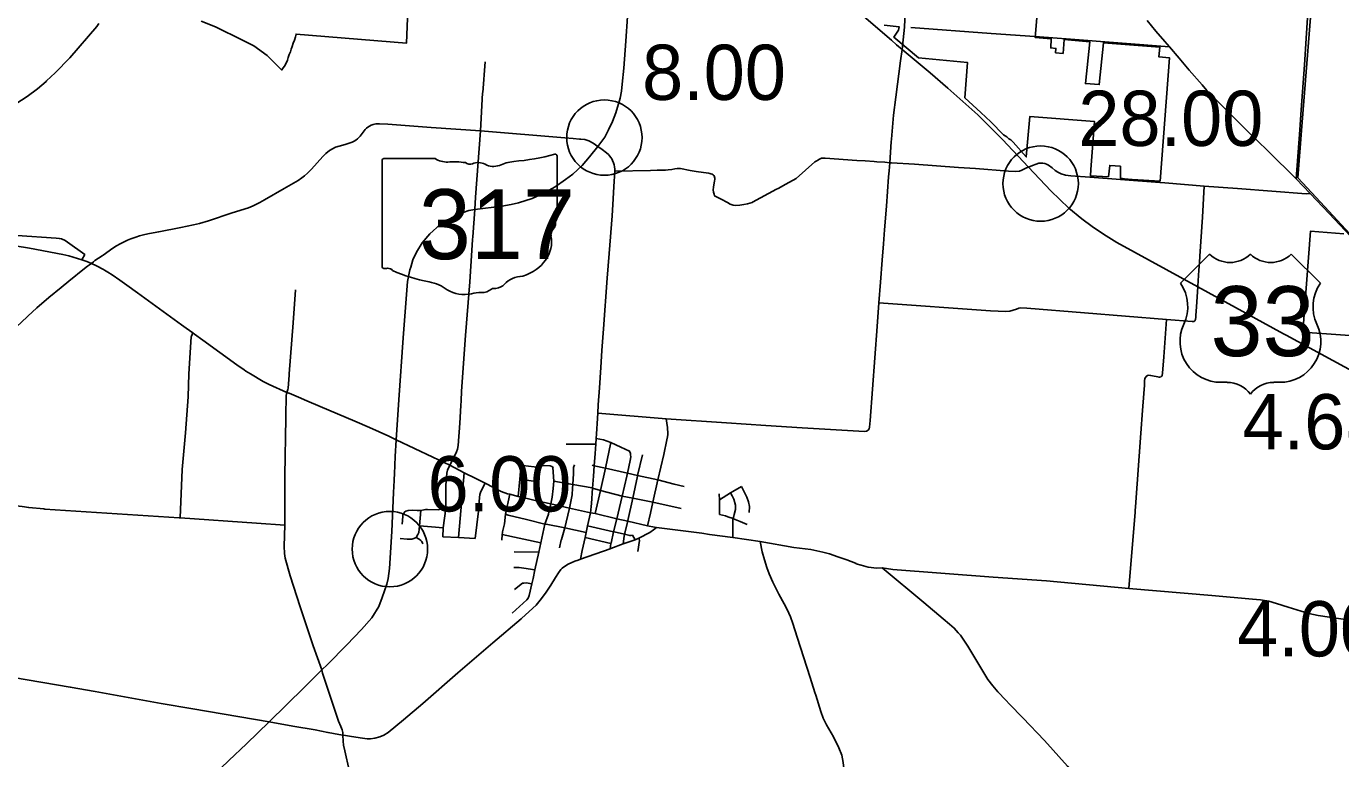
# Model space of a CAD drawing. Extents: x 1659811 to 1934326, y 644115 to 934867.
# Drawn here: x 1848780 to 1874937, y 669837 to 684419 of the extents above; entities that cross this region are included whole.
import ezdxf

# ---------------------------------------------------------------- set-up
doc = ezdxf.new("R2010")
doc.units = 0
for name, color, linetype in [('Default', 7, 'Continuous'), ('GM_X_City_Street', 7, 'Continuous'), ('GM_X_Corporation', 7, 'Continuous'), ('GM_X_County_Road', 7, 'Continuous'), ('GM_X_Interstate_Route', 7, 'Continuous'), ('GM_X_State_Route', 7, 'Continuous'), ('GM_X_State_Shield', 7, 'Continuous'), ('GM_X_Township_Road', 7, 'Continuous'), ('GM_X_US_Route', 7, 'Continuous'), ('GM_X_US_Shield', 7, 'Continuous')]:
    doc.layers.add(name, color=color, linetype=linetype)

msp = doc.modelspace()

# ---------------------------------------------------------------- linework, layer by layer
at = {"layer": 'Default'}
for centre in [(1860284, 682203), (1868966, 681287), (1856015, 674010)]:
    msp.add_circle(centre, 750, dxfattribs=at)
at = {"layer": 'GM_X_City_Street'}
for points in [[(1866232, 684150), (1866259, 684403), (1866289, 685179), (1866306, 685614)], [(1866382, 684394), (1867983, 684278), (1868853, 684214)], [(1857862, 683100), (1857912, 683710)], [(1857819, 682336), (1857861, 683093), (1857862, 683100)], [(1850291, 679851), (1850307, 679862), (1850502, 679999), (1850578, 680046), (1850646, 680085), (1850729, 680130), (1850795, 680161), (1850860, 680186), (1850958, 680222), (1851033, 680246), (1851141, 680274), (1851233, 680295), (1851417, 680330), (1851854, 680412), (1852107, 680464), (1852226, 680493), (1852404, 680544), (1852879, 680702), (1853203, 680808), (1853298, 680846), (1853426, 680912), (1853522, 680967), (1853910, 681193), (1854189, 681352), (1854261, 681400), (1854318, 681445), (1854378, 681497), (1854453, 681572), (1854570, 681699), (1854684, 681827), (1854744, 681888), (1854816, 681949), (1854871, 681982), (1854933, 682010), (1855003, 682031), (1855128, 682068), (1855265, 682112), (1855307, 682133), (1855338, 682154), (1855372, 682181), (1855399, 682207), (1855422, 682234), (1855522, 682365), (1855552, 682391), (1855579, 682412), (1855608, 682431), (1855645, 682450), (1855680, 682462), (1855708, 682470), (1855738, 682474), (1855770, 682476), (1855812, 682476), (1855976, 682468), (1856838, 682407), (1857819, 682336), (1859494, 682198), (1859660, 682184), (1859789, 682175), (1859814, 682172)], [(1857662, 680176), (1857665, 680229), (1857704, 680773), (1857718, 681019), (1857819, 682336)], [(1859814, 682172), (1859893, 682164), (1859935, 682152), (1859974, 682139), (1860060, 682093), (1860156, 682029), (1860241, 681965), (1860329, 681899), (1860364, 681866), (1860388, 681838), (1860410, 681809), (1860430, 681778), (1860444, 681747), (1860464, 681703), (1860478, 681662), (1860486, 681621), (1860490, 681577), (1860492, 681535)], [(1865951, 681544), (1865963, 681704), (1865992, 682119), (1865997, 682174)], [(1863741, 681190), (1863892, 681274), (1864098, 681392), (1864474, 681719), (1864509, 681742), (1864533, 681756), (1864567, 681774), (1864606, 681792), (1864653, 681792)], [(1865704, 681722), (1865868, 681711), (1865963, 681704), (1865996, 681703), (1866454, 681671), (1867331, 681607), (1867669, 681585), (1868328, 681536), (1868469, 681528), (1868543, 681537), (1868593, 681555), (1868685, 681599), (1868685, 681599)], [(1860247, 678135), (1860266, 678393), (1860341, 679406), (1860379, 679897), (1860436, 680648), (1860456, 680984), (1860475, 681227), (1860492, 681535)], [(1860492, 681535), (1861199, 681551), (1861335, 681555), (1861455, 681558), (1861492, 681557)], [(1861492, 681557), (1861502, 681557), (1861556, 681559), (1861629, 681570), (1861687, 681581), (1861735, 681586), (1861771, 681587), (1861800, 681585), (1861989, 681549), (1862111, 681528), (1862357, 681496), (1862384, 681490), (1862404, 681484), (1862427, 681476), (1862447, 681463), (1862461, 681447), (1862473, 681431), (1862476, 681417), (1862480, 681396), (1862480, 681371), (1862477, 681340), (1862456, 681216), (1862451, 681165), (1862455, 681118), (1862467, 681076), (1862477, 681042), (1862607, 680976), (1862731, 680909), (1862790, 680878), (1862844, 680860), (1862898, 680854), (1862977, 680858), (1863058, 680870), (1863132, 680885), (1863225, 680913), (1863231, 680916)], [(1847456, 680242), (1847735, 680195), (1848561, 680047), (1848847, 679999), (1849507, 679879), (1849629, 679848), (1849888, 679772), (1849983, 679737), (1850029, 679718), (1850075, 679699)], [(1847735, 680195), (1847747, 680281), (1847763, 680306), (1847815, 680306), (1849376, 680203), (1849436, 680197), (1849480, 680187), (1849554, 680155), (1849692, 680058), (1849854, 679940), (1849942, 679875), (1849888, 679772)], [(1850117, 679731), (1850147, 679753), (1850291, 679851)], [(1848303, 678175), (1848677, 678522), (1848813, 678650), (1848988, 678813), (1849229, 679022), (1849471, 679219), (1849626, 679343), (1849941, 679594), (1849997, 679641), (1850075, 679699)], [(1850075, 679699), (1850117, 679731)], [(1850075, 679699), (1850178, 679651), (1850317, 679576), (1850333, 679567), (1850405, 679526), (1850490, 679472), (1850641, 679365), (1850783, 679263), (1850996, 679110), (1851649, 678636), (1851867, 678478)], [(1852124, 678291), (1852293, 678171), (1852973, 677678), (1853115, 677579), (1853151, 677554), (1853239, 677497), (1853496, 677349), (1853612, 677287), (1853964, 677130), (1854004, 677115)], [(1853964, 677130), (1853984, 677186), (1853988, 677214), (1854008, 677475)], [(1853947, 676655), (1853951, 677068), (1853964, 677130)], [(1854004, 677115), (1854012, 677112), (1854194, 677034), (1854360, 676964), (1854629, 676848), (1855315, 676556), (1855608, 676432), (1855996, 676257), (1856143, 676188)], [(1857211, 675679), (1857307, 675873), (1857343, 675944), (1857362, 676003), (1857372, 676074), (1857405, 676517), (1857425, 676868), (1857431, 676963)], [(1856143, 676188), (1856869, 675838), (1857211, 675679), (1857493, 675528), (1857729, 675414), (1857909, 675320), (1858229, 675159), (1858353, 675112), (1858401, 675102), (1858567, 675061), (1858669, 675037)], [(1860005, 674735), (1860027, 674918), (1860049, 675225), (1860068, 675462), (1860084, 675668), (1860100, 675913), (1860114, 676102), (1860121, 676212), (1860127, 676304)], [(1860121, 676212), (1860267, 676183), (1860415, 676136), (1860610, 676040), (1860784, 675958), (1860801, 675911)], [(1859525, 676101), (1860114, 676102)], [(1860101, 674719), (1860206, 675175), (1860309, 675622), (1860415, 676136)], [(1860398, 674016), (1860415, 674121), (1860417, 674131), (1860468, 674353), (1860529, 674616), (1860637, 675067), (1860732, 675465), (1860743, 675520), (1860794, 675775), (1860809, 675847), (1860803, 675889), (1860801, 675911)], [(1857069, 674256), (1857077, 674436), (1857126, 674822), (1857130, 675067), (1857131, 675278), (1857149, 675519), (1857161, 675580), (1857211, 675679)], [(1858567, 675061), (1858600, 675406), (1858619, 675635), (1858626, 675670)], [(1858626, 675670), (1858664, 675673), (1858886, 675651), (1858968, 675641), (1859031, 675665), (1859036, 675667), (1859045, 675668)], [(1859045, 675668), (1859101, 675674), (1859207, 675666), (1859237, 675652), (1859253, 675646)], [(1859585, 674801), (1859590, 674824), (1859641, 675093), (1859652, 675225), (1859654, 675295), (1859670, 675517), (1859672, 675634), (1859690, 675691)], [(1860042, 675679), (1860084, 675668), (1860309, 675622), (1860743, 675520), (1860945, 675477), (1861348, 675389), (1861674, 675303), (1861674, 675303)], [(1860751, 674580), (1860847, 675025), (1860942, 675464), (1860945, 675477), (1861044, 675884)], [(1861141, 674476), (1861199, 674729), (1861246, 674946), (1861348, 675389), (1861464, 675893), (1861465, 675896)], [(1857380, 674241), (1857493, 675528)], [(1858600, 675406), (1858871, 675360)], [(1859173, 674715), (1859217, 674909), (1859242, 675045), (1859263, 675216), (1859277, 675363), (1859261, 675638), (1859263, 675628), (1859253, 675646)], [(1857714, 674224), (1857782, 674765), (1857798, 675037), (1857805, 675095), (1857817, 675140), (1857840, 675187), (1857909, 675320)], [(1859277, 675363), (1859654, 675295), (1860040, 675227)], [(1860040, 675227), (1860049, 675225), (1860206, 675175), (1860637, 675067), (1860847, 675025), (1861246, 674946), (1861813, 674817)], [(1861674, 675303), (1861872, 675258)], [(1862572, 674994), (1862793, 675132), (1862839, 675160), (1863013, 675254)], [(1862840, 674240), (1862843, 674606), (1862847, 674619), (1862855, 674642), (1862869, 674698), (1862894, 674802), (1862893, 674888), (1862857, 675003), (1862824, 675074), (1862793, 675132)], [(1863168, 674737), (1863170, 674857), (1863155, 674952), (1863122, 675042), (1863013, 675254)], [(1846880, 674793), (1846958, 674789), (1847073, 674789), (1847185, 674805), (1847331, 674838), (1847483, 674885), (1847613, 674910), (1847696, 674919), (1847787, 674921), (1848522, 674877), (1848695, 674859), (1848830, 674836), (1849131, 674810)], [(1858257, 674353), (1858298, 674513), (1858319, 674709), (1858401, 675102)], [(1858669, 675037), (1858932, 674974), (1859217, 674909), (1859590, 674824), (1860005, 674735), (1860101, 674719), (1860529, 674616), (1860748, 674568), (1861141, 674476), (1861281, 674450)], [(1862577, 674702), (1862577, 674909), (1862572, 674994), (1862566, 675109)], [(1849131, 674810), (1849151, 674808), (1851819, 674632)], [(1856259, 674506), (1856270, 674658), (1856276, 674702), (1856290, 674728), (1856310, 674754), (1856332, 674768), (1856376, 674782), (1856475, 674787), (1856557, 674781), (1856629, 674779)], [(1856539, 674242), (1856571, 674298), (1856589, 674342), (1856606, 674472), (1856629, 674779)], [(1856629, 674779), (1856693, 674791), (1856723, 674797), (1856765, 674800), (1856974, 674791), (1857003, 674797)], [(1857003, 674797), (1857126, 674822)], [(1858319, 674709), (1858368, 674687), (1858734, 674599)], [(1858447, 672732), (1858741, 673000), (1858767, 673034), (1858789, 673090), (1858841, 673322), (1858864, 673426), (1858902, 673599), (1858977, 673948), (1859018, 674134), (1859099, 674510), (1859170, 674704), (1859173, 674715)], [(1859428, 674203), (1859500, 674433), (1859585, 674801)], [(1859806, 673807), (1859808, 673808), (1859845, 673982), (1859899, 674242), (1859919, 674339), (1859950, 674475), (1860005, 674735)], [(1862577, 674702), (1862696, 674671), (1862741, 674653), (1862847, 674619), (1862855, 674616), (1862986, 674563), (1863126, 674500)], [(1870847, 674748), (1870850, 674781), (1870855, 674853)], [(1854233, 672859), (1854030, 673476), (1853929, 673830), (1853917, 673924), (1853914, 674072), (1853927, 674485)], [(1856606, 674472), (1856841, 674454), (1856841, 674454)], [(1856841, 674454), (1857077, 674436)], [(1858246, 674186), (1858252, 674302), (1858254, 674341), (1858257, 674353)], [(1858734, 674599), (1859099, 674510), (1859124, 674505), (1859500, 674433), (1859919, 674339)], [(1859950, 674475), (1860468, 674353), (1860477, 674351), (1860687, 674307), (1860790, 674281), (1860813, 674279), (1860843, 674286), (1860896, 674197)], [(1860410, 674021), (1860655, 674113), (1860896, 674197), (1860971, 674226), (1861189, 674344), (1861264, 674392), (1861324, 674441)], [(1860685, 674301), (1860687, 674307), (1860748, 674568), (1860748, 674568), (1860751, 674580)], [(1861281, 674450), (1861324, 674441), (1862222, 674325), (1862373, 674304)], [(1856220, 674223), (1856360, 674205), (1856452, 674206), (1856495, 674220), (1856539, 674242)], [(1856672, 674115), (1856653, 674159), (1856629, 674182), (1856599, 674208), (1856539, 674242)], [(1857069, 674256), (1857380, 674241), (1857714, 674224)], [(1858252, 674302), (1859018, 674134)], [(1859393, 674038), (1859426, 674195), (1859428, 674203)], [(1859899, 674242), (1860415, 674121)], [(1860655, 674113), (1860678, 674271), (1860685, 674301)], [(1860953, 673963), (1860982, 674183), (1860979, 674205), (1860971, 674226)], [(1858488, 673957), (1858977, 673948)], [(1859808, 673808), (1860398, 674016), (1860410, 674021)], [(1858481, 673646), (1858589, 673642), (1858679, 673633), (1858902, 673599)], [(1859433, 673618), (1859447, 673630), (1859471, 673651), (1859562, 673712), (1859697, 673771), (1859765, 673793), (1859806, 673807)], [(1858497, 673209), (1858656, 673329), (1858680, 673335), (1858726, 673339), (1858841, 673322)], [(1854688, 671502), (1854675, 671541), (1854661, 671604), (1854486, 672082), (1854233, 672859)], [(1873383, 672991), (1873504, 672971), (1873662, 672930), (1873894, 672853), (1874153, 672772), (1874300, 672731), (1874486, 672690), (1875618, 672523), (1876085, 672438)], [(1855134, 670298), (1855213, 670285), (1855425, 670250), (1855514, 670239), (1855561, 670236), (1855627, 670231), (1855715, 670247), (1855815, 670274), (1855892, 670309), (1855978, 670357), (1856284, 670609), (1856670, 670935), (1857365, 671549), (1858064, 672147), (1858630, 672623), (1858644, 672636)], [(1846662, 671785), (1846668, 671784), (1848424, 671472), (1848523, 671455), (1849656, 671265), (1850152, 671175), (1851462, 670939), (1852096, 670831)]]:
    msp.add_lwpolyline(points, dxfattribs=at)
at = {"layer": 'GM_X_Corporation'}
for points in [[(1856501, 687880), (1856343, 684081), (1854149, 684264), (1854136, 684210), (1854118, 684142), (1854094, 684080), (1854068, 684014), (1854054, 683962), (1854036, 683910), (1854012, 683858), (1853990, 683800), (1853976, 683745), (1853960, 683695), (1853916, 683627), (1853870, 683563), (1853862, 683548), (1853573, 683837), (1853305, 684032), (1853083, 684145), (1852547, 684407), (1852261, 684521)], [(1868979, 685617), (1868858, 684195), (1869178, 684171), (1869167, 683987), (1869270, 683977), (1869263, 683892), (1869412, 683880), (1869435, 684154), (1869942, 684111), (1869856, 683280), (1870132, 683259), (1870216, 684093), (1871335, 684006), (1871321, 683808), (1871527, 683792), (1871344, 681336), (1870784, 681372), (1870634, 681382), (1870556, 681393), (1870553, 681633), (1870341, 681650), (1870314, 681422), (1869958, 681440), (1869964, 681569), (1870039, 682521), (1868748, 682620), (1868680, 681819), (1868422, 682109), (1868374, 682157), (1868335, 682179), (1868291, 682218), (1868224, 682261), (1867973, 682514), (1867775, 682701), (1867460, 682994), (1867508, 683699), (1866537, 683789), (1866043, 684203), (1866138, 684340), (1866150, 684410), (1865849, 684442)], [(1875122, 680290), (1874447, 681012), (1874086, 681399), (1874157, 682347), (1874416, 685600)], [(1876430, 678173), (1874185, 678331), (1874334, 680339), (1874999, 680290)]]:
    msp.add_lwpolyline(points, dxfattribs=at)
at = {"layer": 'GM_X_County_Road'}
for points in [[(1874049, 681380), (1874122, 682361), (1874149, 682757), (1874214, 683655), (1874258, 684283), (1874286, 684692), (1874332, 685369), (1874393, 686246), (1874409, 686478)], [(1871083, 684532), (1871258, 684324), (1871437, 684117), (1871533, 684008), (1871722, 683784), (1871920, 683547), (1872179, 683254), (1872274, 683139), (1873057, 682359), (1873496, 681932), (1874049, 681380), (1874327, 681093), (1874705, 680695), (1875130, 680244)], [(1866082, 683008), (1866175, 683732), (1866211, 683955), (1866232, 684150)], [(1865997, 682174), (1866035, 682647), (1866082, 683008)], [(1861513, 676603), (1862717, 676522), (1863496, 676469), (1864217, 676423), (1865458, 676355), (1865501, 676361), (1865531, 676379), (1865551, 676407), (1865559, 676440), (1865570, 676568), (1865711, 678443), (1865747, 678914), (1865778, 679328), (1865812, 679763), (1865837, 680091), (1865860, 680367), (1865898, 680836), (1865941, 681419), (1865951, 681544)], [(1857431, 676963), (1857442, 677153), (1857522, 678265), (1857604, 679332), (1857649, 679956), (1857662, 680176)], [(1851867, 678478), (1851960, 678412), (1852093, 678313), (1852124, 678291)], [(1860145, 676618), (1860153, 676717), (1860162, 676886), (1860184, 677224), (1860212, 677628), (1860234, 677965), (1860247, 678135)], [(1860127, 676304), (1860144, 676609), (1860145, 676618)], [(1861465, 675896), (1861529, 676184), (1861543, 676244), (1861549, 676293), (1861547, 676345), (1861543, 676392), (1861537, 676434), (1861513, 676603)], [(1862373, 674304), (1862840, 674240), (1863384, 674164), (1864053, 674044), (1864390, 674002), (1864630, 673951), (1864765, 673913), (1864929, 673857), (1865112, 673799), (1865280, 673728), (1865294, 673721), (1865297, 673720)], [(1864489, 671105), (1864473, 671154), (1864377, 671452), (1864120, 672259), (1864031, 672532), (1863985, 672663), (1863920, 672805), (1863863, 672918), (1863756, 673115), (1863634, 673354), (1863566, 673518), (1863515, 673643), (1863470, 673796), (1863426, 673955), (1863384, 674164)], [(1858644, 672636), (1858928, 672897), (1859009, 672997), (1859110, 673134), (1859218, 673292), (1859309, 673446), (1859370, 673541), (1859420, 673607), (1859433, 673618)], [(1865297, 673720), (1865397, 673692), (1865536, 673653), (1865708, 673630), (1865811, 673635)], [(1865811, 673635), (1866022, 673605), (1868024, 673455), (1869083, 673378), (1870724, 673229), (1872375, 673088), (1873180, 673017), (1873341, 672998), (1873383, 672991)], [(1865811, 673635), (1866638, 672945), (1867028, 672621)], [(1867028, 672621), (1867153, 672517), (1867245, 672439), (1867323, 672345), (1867374, 672295), (1867453, 672176), (1867515, 672079), (1867696, 671779), (1867917, 671415), (1868012, 671286), (1868112, 671166), (1868274, 671000)], [(1855082, 670307), (1855077, 670356), (1855067, 670412), (1855039, 670479), (1854992, 670586), (1854875, 670941), (1854688, 671502)], [(1864970, 668444), (1865034, 669256), (1865054, 669593), (1865039, 669765), (1865007, 669911), (1864949, 670055), (1864841, 670275), (1864704, 670513), (1864640, 670647), (1864594, 670775), (1864489, 671105)], [(1868274, 671000), (1868347, 670926), (1868610, 670653), (1869044, 670197), (1869498, 669689), (1869989, 669106), (1870557, 668457), (1870814, 668157), (1871379, 667510), (1871553, 667320), (1871913, 666946), (1872824, 666007), (1872995, 665840), (1873212, 665623), (1873465, 665411), (1873709, 665202), (1873723, 665190)], [(1852096, 670831), (1853612, 670573)], [(1853612, 670573), (1854085, 670484), (1854528, 670409), (1854778, 670361)], [(1854778, 670361), (1854785, 670360), (1854999, 670321), (1855082, 670307)], [(1855343, 668206), (1855343, 668329), (1855342, 668614), (1855345, 668809), (1855341, 668910), (1855330, 668988), (1855286, 669200), (1855262, 669308), (1855207, 669612), (1855120, 669991), (1855095, 670107), (1855089, 670185), (1855082, 670307)], [(1855082, 670307), (1855134, 670298)]]:
    msp.add_lwpolyline(points, dxfattribs=at)
at = {"layer": 'GM_X_Interstate_Route'}
for points in [[(1850224, 684472), (1850183, 684418), (1849646, 683789), (1849356, 683495), (1849183, 683330), (1849173, 683321)], [(1849173, 683321), (1849003, 683172), (1848798, 683022), (1848329, 682717), (1848032, 682542), (1847692, 682384), (1847492, 682293), (1847427, 682266), (1847361, 682239), (1847337, 682230)]]:
    msp.add_lwpolyline(points, dxfattribs=at)
at = {"layer": 'GM_X_State_Route'}
for points in [[(1856430, 679624), (1856472, 679768), (1856544, 679921), (1856661, 680105), (1856809, 680290), (1857017, 680470), (1857125, 680541), (1857279, 680626), (1857475, 680711), (1857585, 680749), (1857704, 680773), (1858242, 680836), (1858431, 680872), (1858575, 680904), (1858844, 680992), (1859077, 681097), (1859302, 681221), (1859512, 681366), (1859654, 681474), (1859840, 681648), (1859988, 681821), (1860156, 682029), (1860291, 682215), (1860366, 682357), (1860443, 682525), (1860511, 682693), (1860595, 682989), (1860623, 683127), (1860637, 683268), (1860670, 683583), (1860712, 684123), (1860745, 684612)], [(1856143, 676188), (1856195, 676985), (1856281, 678215), (1856367, 679337), (1856415, 679572), (1856430, 679624)], [(1856102, 675399), (1856109, 675507), (1856120, 675852), (1856143, 676188)], [(1854772, 671716), (1855159, 672106), (1855452, 672408), (1855656, 672644), (1855793, 672869), (1855865, 673048), (1855955, 673310), (1855982, 673423), (1856008, 673625), (1856056, 674364), (1856086, 675140), (1856101, 675376), (1856102, 675399)], [(1848819, 666696), (1849099, 666688), (1849232, 666701), (1849354, 666722), (1849455, 666750), (1849554, 666780), (1849673, 666832), (1849786, 666895), (1850303, 667340), (1851168, 668195), (1852000, 669022), (1852811, 669805), (1853162, 670133), (1853612, 670573), (1854310, 671256), (1854583, 671527)], [(1854583, 671527), (1854661, 671604), (1854772, 671716)]]:
    msp.add_lwpolyline(points, dxfattribs=at)
at = {"layer": 'GM_X_State_Shield'}
for p, q in [((1855863, 681748), (1855863, 679634)), ((1856916, 681784), (1855897, 681784)), ((1859343, 680731), (1859343, 681836)), ((1859343, 680731), (1859343, 680731))]:
    msp.add_line(p, q, dxfattribs=at)
for centre, major_axis, start_param, end_param in [((1855902, 681752), (40.3, 0), 1.712693, 3.28349), ((1857159, 682029), (391, 0), 4.042523, 4.731795), ((1857289, 680597), (1404, 0), 1.404758, 1.657858), ((1857607, 681763), (113, 0), 3.836095, 5.185415), ((1857773, 681519), (235, 0), 0.950623, 2.079405), ((1858076, 681854), (282, 0), 4.081561, 5.145723), ((1858574, 681138), (743, 0), 1.699011, 2.107814), ((1858103, 684665), (3691, 0), 4.814394, 5.042369), ((1859304, 681841), (38.7, 0), 6.141152, 7.989035), ((1859334, 680650), (60, 0), 1.883978, 3.671073), ((1858953, 680510), (360, 0), 5.934695, 6.695948), ((1859302, 680727), (41.5, 0), 5.05454, 6.418171), ((1859482, 680268), (262, 0), 2.387724, 3.262537), ((1858310, 680128), (923, 0), 5.101752, 6.440018), ((1855903, 679630), (40.7, 0), 3.00124, 4.508301), ((1855909, 679846), (310, 0), 4.665946, 4.897461), ((1855973, 679512), (112, 0), 0.519207, 1.627899), ((1857386, 681411), (2665, 0), 4.195997, 4.488961), ((1856591, 678685), (834, 0), 0.823519, 1.323587), ((1858699, 679041), (506, 0), 1.647645, 2.488434), ((1857493, 679502), (529, 0), 4.026481, 4.996735), ((1857799, 678771), (435, 0), 1.495662, 1.94098), ((1857837, 679344), (282, 0), 4.691044, 5.507374), ((1858093, 679139), (79.4, 0), 1.147584, 2.315152), ((1858059, 679429), (298, 0), 4.937069, 5.64225)]:
    msp.add_ellipse(centre, major_axis=major_axis, ratio=0.8, start_param=start_param, end_param=end_param, dxfattribs=at)
at = {"layer": 'GM_X_Township_Road'}
for points in [[(1868853, 684214), (1868859, 684213), (1869559, 684160), (1871533, 684008)], [(1864653, 681792), (1864678, 681792), (1865310, 681749), (1865473, 681738), (1865653, 681725), (1865704, 681722)], [(1868685, 681599), (1868727, 681617), (1868801, 681646), (1868878, 681677), (1868931, 681692), (1868971, 681695), (1869008, 681693), (1869048, 681687), (1869083, 681674), (1869119, 681656), (1869192, 681602), (1869255, 681548), (1869306, 681514), (1869375, 681480), (1869460, 681455), (1869566, 681444), (1869944, 681416), (1871340, 681308), (1871439, 681300)], [(1863231, 680916), (1863712, 681174), (1863741, 681190)], [(1871439, 681300), (1872221, 681239), (1872885, 681187), (1874250, 681084), (1874327, 681093)], [(1872115, 679561), (1872124, 679714), (1872134, 679844), (1872185, 680621), (1872221, 681239)], [(1872096, 679246), (1872115, 679561)], [(1854008, 677475), (1854010, 677499), (1854088, 678515), (1854140, 679172)], [(1872073, 678932), (1872095, 679234), (1872096, 679246)], [(1865747, 678914), (1867969, 678757), (1868273, 678741), (1868351, 678745), (1868482, 678785), (1868531, 678810), (1868569, 678814), (1868688, 678808), (1869841, 678714), (1871471, 678584)], [(1872055, 678670), (1872060, 678744), (1872073, 678932)], [(1871363, 677445), (1871375, 677453), (1871383, 677467), (1871391, 677510), (1871414, 677839), (1871471, 678584), (1871981, 678540), (1872015, 678542), (1872035, 678556), (1872047, 678582), (1872052, 678630), (1872055, 678670)], [(1851844, 674630), (1851881, 675592), (1851949, 676325), (1851998, 677040), (1852017, 677499), (1852063, 678236), (1852065, 678251), (1852093, 678313)], [(1870962, 676320), (1870995, 676767), (1871021, 677107), (1871031, 677272), (1871035, 677362), (1871042, 677408), (1871063, 677444), (1871092, 677465), (1871119, 677471), (1871152, 677467), (1871337, 677434), (1871324, 677432), (1871357, 677442), (1871363, 677445)], [(1860153, 676717), (1861513, 676603)], [(1853927, 674485), (1853928, 675474), (1853947, 676619), (1853947, 676655)], [(1870855, 674853), (1870962, 676320)], [(1851819, 674632), (1851844, 674630), (1853364, 674525), (1853927, 674485)], [(1870724, 673229), (1870847, 674748)]]:
    msp.add_lwpolyline(points, dxfattribs=at)
at = {"layer": 'GM_X_US_Route'}
for points in [[(1863517, 686267), (1864034, 685824), (1865077, 684934), (1865996, 684144), (1866100, 684050), (1866211, 683955), (1866765, 683491), (1867122, 683185), (1867715, 682659), (1867973, 682400), (1868205, 682168), (1868727, 681617), (1869171, 681145), (1869529, 680799), (1869787, 680588), (1869991, 680435), (1870216, 680279), (1870485, 680114), (1872095, 679234), (1873802, 678296), (1873853, 678268)], [(1873853, 678268), (1875010, 677636), (1875486, 677386), (1875669, 677296), (1875942, 677169), (1876447, 676960)]]:
    msp.add_lwpolyline(points, dxfattribs=at)
at = {"layer": 'GM_X_US_Shield'}
for p, q in [((1872327, 679883), (1871747, 679303)), ((1874532, 679303), (1873952, 679883)), ((1872560, 677331), (1872676, 677331)), ((1873604, 677331), (1873720, 677331))]:
    msp.add_line(p, q, dxfattribs=at)
for centre, radius, start, end in [((1872734, 680297), 580, 225.573, 314.427), ((1873546, 680297), 580, 225.573, 314.427), ((1871082, 678837), 812, 334.5471, 35.0009), ((1875197, 678837), 812, 144.9991, 205.4529), ((1872550, 678143), 812, 154.8319, 270.6383), ((1873729, 678143), 812, 269.3617, 25.1681), ((1872676, 676750), 580, 36.8699, 90), ((1873604, 676750), 580, 90, 143.1301)]:
    msp.add_arc(centre, radius, start, end, dxfattribs=at)

# ---------------------------------------------------------------- texts
at = {"layer": 'Default'}
for s, p in [('8.00', (1861034, 682953)), ('28.00', (1869716, 682037)), ('4.68', (1872984, 675996)), ('6.00', (1856765, 674760)), ('4.00', (1872877, 671874))]:
    msp.add_text(s, height=1100, dxfattribs=at).set_placement(p)
at = {"layer": 'GM_X_State_Shield'}
msp.add_text('317', height=1392.2, dxfattribs=at).set_placement((1856592, 679783))
at = {"layer": 'GM_X_US_Shield'}
msp.add_text('33', height=1392.2, dxfattribs=at).set_placement((1872347, 677853))

doc.saveas('drawing.dxf')
